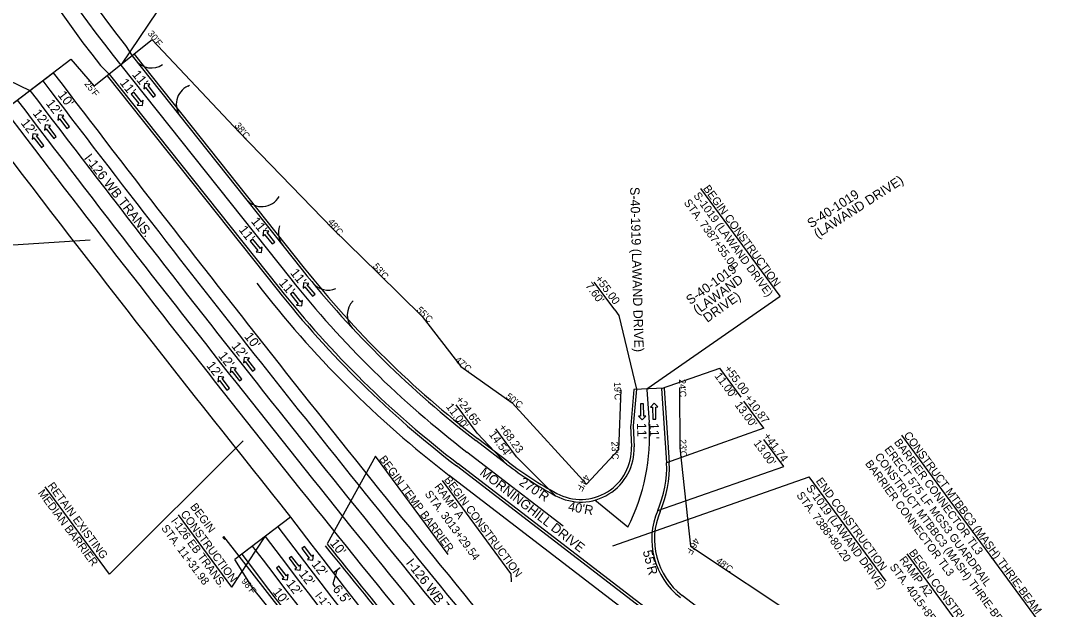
# Model space of a CAD drawing. Extents: x 1966090 to 1975830, y 788086 to 801233.
# Drawn here: x 1969648 to 1970416, y 797669 to 798102 of the extents above; entities that cross this region are included whole.
import ezdxf

# ---------------------------------------------------------------- set-up
doc = ezdxf.new("R2010")
doc.units = 0
for name, color, linetype in [('BR_PRESTRESSED BEAM', 7, 'Continuous'), ('BR_PROPOSED_DRAINAGE', 7, 'Continuous'), ('RD_EX_Driveway_txCode', 7, 'Continuous'), ('RD_EX_RW_TX', 7, 'Continuous'), ('RD_EX_SU_Gas', 7, 'Continuous'), ('RD_EX_SU_H2O', 7, 'Continuous'), ('RD_EX_Survey_Limits', 7, 'Continuous'), ('RD_EX_TX_Dam_ELEV', 7, 'Continuous'), ('RD_PD_PaveShd', 7, 'Continuous'), ('RD_PD_SuperShp2', 7, 'Continuous'), ('RD_Sketch4', 7, 'Continuous'), ('RD_Sketch6', 7, 'Continuous'), ('RD_Sketch8', 7, 'Continuous'), ('RD_Sketch9', 7, 'Continuous')]:
    doc.layers.add(name, color=color, linetype=linetype)

msp = doc.modelspace()

# ---------------------------------------------------------------- linework, layer by layer
at = {"layer": 'BR_PRESTRESSED BEAM'}
for p, q in [((1969800.02, 797714.91), (1969799.23, 797714.29)), ((1969799.23, 797714.29), (1969800.66, 797712.87)), ((1969801.25, 797713.33), (1969800.02, 797714.91)), ((1969844.28, 797658.12), (1969800.02, 797714.91)), ((1969800.66, 797712.87), (1969801.25, 797713.33))]:
    msp.add_line(p, q, dxfattribs=at)
at = {"layer": 'BR_PROPOSED_DRAINAGE'}
for p, q in [((1969746.43, 798087.34), (1969702.87, 798052.71)), ((1969746.43, 798087.34), (1969811.88, 798018)), ((1969620.66, 798023.58), (1969685.48, 798072.84)), ((1969685.48, 798072.84), (1969702.87, 798052.71)), ((1969811.88, 798018), (1969881.77, 797945.81)), ((1969881.77, 797945.81), (1969915.76, 797912.56)), ((1969915.76, 797912.56), (1969948.84, 797879.91)), ((1969948.84, 797879.91), (1969977.8, 797842.54)), ((1969977.8, 797842.54), (1970016.25, 797815.18)), ((1970097.89, 797824.97), (1970095.96, 797779.88)), ((1970141.67, 797826.51), (1970142.06, 797781.49)), ((1970072.06, 797754.16), (1970016.25, 797815.18)), ((1970095.96, 797779.88), (1970072.06, 797754.16)), ((1970142.06, 797781.49), (1970150.13, 797707.64)), ((1969850.13, 797729.55), (1969808.29, 797697.75)), ((1970150.13, 797707.64), (1970257.33, 797636.55)), ((1969822.69, 797674.98), (1969808.29, 797697.75)), ((1969822.69, 797674.98), (1969851.02, 797639.66))]:
    msp.add_line(p, q, dxfattribs=at)
msp.add_arc((1981199.22, 806822.99), 14542.78, 217.233941, 218.703425, dxfattribs=at)
at = {"layer": 'RD_EX_Driveway_txCode'}
for points in [[(1969747.1, 798044.55), (1969748.98, 798046.03), (1969743.32, 798053.24), (1969744.6, 798054.25), (1969740.63, 798054.72), (1969740.15, 798050.75), (1969741.43, 798051.76)], [(1969732.6, 798048.27), (1969730.72, 798046.78), (1969736.41, 798039.59), (1969735.13, 798038.58), (1969739.11, 798038.11), (1969739.57, 798042.09), (1969738.29, 798041.08)], [(1969682.46, 798020.92), (1969684.36, 798022.38), (1969678.77, 798029.65), (1969680.06, 798030.64), (1969676.1, 798031.16), (1969675.58, 798027.2), (1969676.87, 798028.19)], [(1969672.58, 798013.53), (1969674.48, 798014.99), (1969668.89, 798022.26), (1969670.19, 798023.26), (1969666.22, 798023.78), (1969665.7, 798019.81), (1969666.99, 798020.8)], [(1969663.3, 798006.67), (1969665.2, 798008.14), (1969659.61, 798015.41), (1969660.91, 798016.4), (1969656.94, 798016.92), (1969656.42, 798012.96), (1969657.71, 798013.95)], [(1969836.35, 797934.34), (1969838.23, 797935.82), (1969832.57, 797943.03), (1969833.85, 797944.04), (1969829.88, 797944.52), (1969829.4, 797940.55), (1969830.68, 797941.55)], [(1969821.85, 797938.06), (1969819.97, 797936.57), (1969825.66, 797929.38), (1969824.38, 797928.37), (1969828.36, 797927.91), (1969828.82, 797931.88), (1969827.54, 797930.87)], [(1969866.67, 797895.18), (1969868.52, 797896.72), (1969862.66, 797903.78), (1969863.92, 797904.82), (1969859.93, 797905.19), (1969859.56, 797901.2), (1969860.82, 797902.24)], [(1969852.08, 797898.17), (1969850.2, 797896.69), (1969855.86, 797889.48), (1969854.58, 797888.47), (1969858.55, 797887.99), (1969859.03, 797891.97), (1969857.75, 797890.96)], [(1969821.63, 797838.98), (1969823.53, 797840.45), (1969817.95, 797847.72), (1969819.24, 797848.71), (1969815.27, 797849.23), (1969814.75, 797845.27), (1969816.04, 797846.26)], [(1969811.75, 797831.6), (1969813.66, 797833.06), (1969808.07, 797840.33), (1969809.36, 797841.32), (1969805.39, 797841.84), (1969804.87, 797837.88), (1969806.16, 797838.87)], [(1969802.47, 797824.74), (1969804.38, 797826.2), (1969798.79, 797833.48), (1969800.08, 797834.47), (1969796.11, 797834.99), (1969795.59, 797831.02), (1969796.88, 797832.02)], [(1970114.87, 797814.49), (1970112.47, 797814.45), (1970112.63, 797805.28), (1970111, 797805.25), (1970113.88, 797802.47), (1970116.66, 797805.34), (1970115.03, 797805.32)], [(1970121.7, 797802.87), (1970124.1, 797802.91), (1970123.95, 797812.08), (1970125.58, 797812.11), (1970122.7, 797814.89), (1970119.92, 797812.02), (1970121.55, 797812.04)], [(1969860.47, 797707.37), (1969858.57, 797705.91), (1969864.15, 797698.64), (1969862.86, 797697.65), (1969866.83, 797697.13), (1969867.35, 797701.09), (1969866.06, 797700.1)], [(1969850.95, 797700.06), (1969849.05, 797698.6), (1969854.64, 797691.33), (1969853.34, 797690.34), (1969857.31, 797689.82), (1969857.83, 797693.78), (1969856.54, 797692.79)], [(1969841.44, 797692.75), (1969839.53, 797691.29), (1969845.12, 797684.02), (1969843.83, 797683.03), (1969847.79, 797682.51), (1969848.31, 797686.47), (1969847.02, 797685.48)]]:
    msp.add_lwpolyline(points, close=True, dxfattribs=at)
at = {"layer": 'RD_EX_SU_Gas'}
msp.add_line((1970103.12, 797721.97), (1970078.27, 797742.23), dxfattribs=at)
for centre, radius, end in [((1981199.22, 806822.99), 14500, 219.566224), ((1981199.22, 806822.99), 14512, 219.566224), ((1978986.99, 804673.34), 11488, 219.351802), ((1978986.99, 804673.34), 11500, 219.351802)]:
    msp.add_arc(centre, radius, 217.233941, end, dxfattribs=at)
at = {"layer": 'RD_EX_Survey_Limits'}
for p, q in [((1969717.03, 798075.77), (1969722.78, 798068.54)), ((1969722.78, 798068.54), (1969850.24, 797908.19)), ((1970117.23, 797825.26), (1970118.99, 797800.47)), ((1970054.6, 797722.82), (1969982.43, 797778.22))]:
    msp.add_line(p, q, dxfattribs=at)
for centre, radius, start, end in [((1970357.34, 798584.73), 817.94, 194.81615, 218.48003), ((1970445.19, 798381.1), 760, 218.48003, 232.49072), ((1969969.37, 797789.87), 150, 333.08573, 4.0555)]:
    msp.add_arc(centre, radius, start, end, dxfattribs=at)
at = {"layer": 'RD_EX_TX_Dam_ELEV'}
msp.add_line((1970237.44, 797554.75), (1969969.03, 797760.77), dxfattribs=at)
msp.add_arc((1970445.19, 798381.1), 782, 217.51585, 232.49072, dxfattribs=at)
at = {"layer": 'RD_PD_PaveShd'}
for p, q in [((1969732.96, 798076.63), (1969860.41, 797916.28)), ((1969712.61, 798060.45), (1969840.06, 797900.1)), ((1970107.6, 797825.31), (1970105.18, 797798.25)), ((1970130.21, 797826.1), (1970134.16, 797770.38)), ((1970105.17, 797798), (1970105.73, 797782.15)), ((1970013.33, 797770.89), (1969990.34, 797788.53)), ((1970242.92, 797561.89), (1969974.51, 797767.91)), ((1970258.75, 797582.51), (1970143.72, 797670.81))]:
    msp.add_line(p, q, dxfattribs=at)
for centre, radius, start, end in [((1981199.22, 806822.99), 14478, 217.233941, 219.566224), ((1970445.19, 798381.1), 747, 218.48003, 232.49072), ((1970445.19, 798381.1), 773, 218.48003, 232.49072), ((1970067.75, 797780.82), 38, 241.77956, 2.0052), ((1970176.51, 797983.48), 268, 232.49072, 241.77956), ((1970049.21, 797767.37), 85, 336.73101, 2.02947), ((1970175.99, 797712.85), 53, 156.73101, 232.49072), ((1978986.99, 804673.34), 11522, 217.233941, 219.351802)]:
    msp.add_arc(centre, radius, start, end, dxfattribs=at)
at = {"layer": 'RD_PD_SuperShp2'}
for p, q in [((1969884.77, 797689.52), (1969881.78, 797679.44)), ((1969887.34, 797691.49), (1969882.2, 797687.55)), ((1969881.78, 797679.44), (1969883.33, 797677.34))]:
    msp.add_line(p, q, dxfattribs=at)
at = {"layer": 'RD_Sketch4'}
msp.add_line((1969773.03, 798052.68), (1969774.42, 798053.34), dxfattribs=at)
for centre, start, end in [((1969745.86, 798081.36), 218.47031, 303.81397), ((1969779.43, 798039.12), 115.24627, 218.47031), ((1969828.49, 797977.37), 218.47031, 330.71955), ((1969855.99, 797942.76), 160.04461, 218.47031), ((1969878.39, 797914.72), 219.44849, 292.71218), ((1969907.66, 797881.27), 135.2692, 222.91891)]:
    msp.add_arc(centre, 15, start, end, dxfattribs=at)
at = {"layer": 'RD_Sketch6'}
for p, q in [((1969825.05, 798219.92), (1969722.78, 798068.54)), ((1969554.27, 798097.16), (1969654.73, 798049.47)), ((1970217.33, 797895.18), (1970157.87, 797975.84)), ((1969699.8, 797937.27), (1969608.11, 797931.2)), ((1970093.23, 797884.86), (1970077.81, 797905.77)), ((1970117.21, 797825.65), (1970217.33, 797895.18)), ((1970188.08, 797819.44), (1970171.99, 797841.27)), ((1969989.98, 797792.53), (1969974.36, 797813.71)), ((1970205.08, 797796.1), (1970190.11, 797816.4)), ((1970019.64, 797774.64), (1970004.02, 797795.82)), ((1970308.2, 797791.08), (1970416.24, 797644.53)), ((1969814.54, 797786.76), (1969714.47, 797686.6)), ((1970220.1, 797767.5), (1970205.13, 797787.82)), ((1969913.95, 797775.1), (1969877.62, 797709.35)), ((1969968.28, 797701.39), (1969913.95, 797775.1)), ((1970019.64, 797774.64), (1970048.84, 797745.58)), ((1970091.92, 797708.05), (1970239.06, 797759.74)), ((1970296.7, 797681.54), (1970239.06, 797759.74)), ((1969714.47, 797686.6), (1969666.13, 797752.19)), ((1970015.34, 797687.23), (1969964, 797756.86)), ((1969806.09, 797676.96), (1969766.06, 797731.26)), ((1969806.09, 797676.96), (1969831.02, 797715.03)), ((1970365.39, 797630.1), (1970312.42, 797701.95)), ((1970015.34, 797687.23), (1970015.61, 797681.01))]:
    msp.add_line(p, q, dxfattribs=at)
for points in [[(1970093.23, 797884.86), (1970096.35, 797880.64), (1970109.62, 797825.38)], [(1970128.21, 797826.03), (1970171.99, 797841.27)], [(1969989.98, 797792.53), (1970012.11, 797769.31)], [(1970205.08, 797796.1), (1970132.16, 797770.27)], [(1970125.46, 797734.58), (1970220.1, 797767.5)]]:
    msp.add_lwpolyline(points, dxfattribs=at)
at = {"layer": 'RD_Sketch8'}
for p, q in [((1969726.43, 798083.24), (1969731.4, 798075.38)), ((1969731.4, 798075.38), (1969858.85, 797915.04)), ((1969707.64, 798068.31), (1969714.17, 798061.7)), ((1969635.62, 798034.94), (1969672.24, 798062.78)), ((1969714.17, 798061.7), (1969841.63, 797901.35)), ((1970109.62, 797825.38), (1970107.17, 797798.07)), ((1970130.21, 797826.1), (1970107.6, 797825.31)), ((1970128.21, 797826.03), (1970132.16, 797770.27)), ((1970107.17, 797798.07), (1970107.73, 797782.22)), ((1970012.11, 797769.31), (1969989.13, 797786.95)), ((1970244.13, 797563.47), (1969975.73, 797769.5)), ((1969850.13, 797729.55), (1969813.5, 797701.71))]:
    msp.add_line(p, q, dxfattribs=at)
for centre, radius, start, end in [((1970357.34, 798584.73), 805.94, 194.81615, 218.48003), ((1970357.34, 798584.73), 829.94, 194.81615, 218.48003), ((1981199.22, 806822.99), 14488, 217.233941, 219.492805), ((1981199.22, 806822.99), 14524, 217.233941, 219.566224), ((1970445.19, 798381.1), 749, 218.48003, 232.49072), ((1970445.19, 798381.1), 771, 218.48003, 232.49072), ((1970067.75, 797780.82), 40, 241.77956, 2.0052), ((1970176.51, 797983.48), 270, 232.49072, 241.77956), ((1970049.21, 797767.37), 83, 336.73101, 2.0052), ((1978986.99, 804673.34), 11476, 217.233941, 219.351802), ((1970175.99, 797712.85), 55, 156.73101, 232.49072), ((1978986.99, 804673.34), 11512, 217.233941, 219.351802)]:
    msp.add_arc(centre, radius, start, end, dxfattribs=at)
at = {"layer": 'RD_Sketch9'}
for radius in [14536, 14534]:
    msp.add_arc((1981199.22, 806822.99), radius, 218.833328, 219.566224, dxfattribs=at)

# ---------------------------------------------------------------- texts
at = {"layer": 'RD_EX_Driveway_txCode'}
for s, rotation, p in [("11'", 308.64673, (1969730.91, 798061.33)), ("11'", 307.53305, (1969721.7, 798055.14)), ("10'", 307.53142, (1969675.23, 798045.97)), ("12'", 307.53142, (1969666.31, 798039.64)), ("12'", 307.53142, (1969647.5, 798025)), ("12'", 307.53142, (1969656.43, 798032.25)), ("11'", 308.64673, (1969820.16, 797951.13)), ("11'", 307.53305, (1969810.95, 797944.94)), ("11'", 308.24073, (1969849.53, 797912.52)), ("11'", 310.16708, (1969840.9, 797904.92)), ("10'", 307.53142, (1969815.11, 797864.81)), ("12'", 307.53142, (1969805.48, 797857.71)), ("12'", 307.53142, (1969795.6, 797850.32)), ("12'", 307.53142, (1969786.68, 797843.07)), ("11'", 271.80335, (1970109.88, 797800.15)), ("11'", 271.80335, (1970119.21, 797800.04)), ("10'", 307.53305, (1969879.31, 797709.81)), ('I-126 WB TRANS.', 307.99228, (1969936.26, 797695.05)), ("12'", 307.53142, (1969855.98, 797686.76)), ("12'", 307.53142, (1969865.49, 797694.07)), ("12'", 307.53142, (1969846.46, 797679.45)), ("10'", 307.53305, (1969836.37, 797673.29))]:
    msp.add_text(s, height=7, rotation=rotation, dxfattribs=at).set_placement(p)
at = {"layer": 'RD_EX_RW_TX'}
for s, rotation, p in [("30'F", 308.48003, (1969742.68, 798092.06)), ("25'F", 308.48003, (1969695.2, 798054.32)), ("38'C", 308.48003, (1969807.89, 798023.02)), ("48'C", 308.48003, (1969877.78, 797950.83)), ("53'C", 311.5084, (1969911.52, 797917.36)), ("55'C", 315.27786, (1969944.29, 797884.42)), ("47'C", 319.04731, (1969972.97, 797846.74)), ("19'C", 272.0052, (1970092.69, 797830.72)), ("24'C", 272.0052, (1970141.45, 797832.91)), ("50'C", 322.49072, (1970011.17, 797819.08)), ("23'C", 272.0052, (1970090.74, 797786.1)), ("23'C", 272.0052, (1970141.84, 797787.89)), ("44'F", 239.9738, (1970070.75, 797761.88)), ("46'F", 239.9738, (1970152.99, 797714.36)), ("48'C", 322.49072, (1970168.79, 797695.79)), ("98'F", 308.78338, (1969812.89, 797681.32))]:
    msp.add_text(s, height=5, rotation=rotation, dxfattribs=at).set_placement(p)
at = {"layer": 'RD_EX_SU_H2O'}
for s, rotation, p in [('I-126 WB TRANS.', 307.99228, (1969694.85, 797998.62)), ('(LAWAND DRIVE)', 32.85686, (1970245.39, 797938.33)), ('S-40-1919 (LAWAND DRIVE)', 271.49911, (1970104.76, 797976.98)), ('S-40-1019 ', 32.85686, (1970240.41, 797946.03)), ('S-40-1019 ', 35.70029, (1970149.82, 797888.49)), ('(LAWAND', 35.70029, (1970155.18, 797881.04)), (' DRIVE)', 35.70029, (1970160.53, 797873.59)), ('MORNINGHILL DRIVE', 322.07869, (1969991.44, 797761.77))]:
    msp.add_text(s, height=7, rotation=rotation, dxfattribs=at).set_placement(p)
at = {"layer": 'RD_PD_SuperShp2'}
msp.add_text("6.5'", height=7, rotation=307.53142, dxfattribs=at).set_placement((1969881.38, 797675.42))
at = {"layer": 'RD_Sketch6'}
for s, height, rotation, p in [('BEGIN CONSTRUCTION', 5.9996, 306.06581, (1970159.23, 797975.91)), ('STA. 7387+55.00', 5.9996, 306.06581, (1970144.68, 797965.31)), ('S-1019 (LAWAND DRIVE)', 5.9996, 306.06581, (1970151.96, 797970.61)), ("7.60'", 6, 306.39766, (1970070.89, 797902.9)), ('+55.00', 6, 306.39766, (1970078.14, 797908.24)), ("11.00'", 6, 306.39766, (1970167.75, 797835.34)), ('+55.00', 6, 306.39766, (1970174.99, 797840.68)), ('+10.87', 6, 306.39766, (1970190.13, 797818.88)), ("11.00'", 6, 306.39766, (1969966.36, 797812.3)), ('+24.65', 6, 306.39766, (1969973.61, 797817.64)), ("13.00'", 6, 306.39766, (1970182.88, 797813.54)), ('+68.23', 6, 306.39766, (1970005.85, 797796.79)), ("14.54'", 6, 306.39766, (1969998.61, 797791.45)), ('+41.74', 6, 306.39766, (1970204.23, 797790.17)), ('CONSTRUCT MTBBC3 (MASH) THRIE-BEAM', 5.9996, 306.42425, (1970309.64, 797790.96)), ("13.00'", 6, 306.39766, (1970196.99, 797784.83)), ('ERECT 575 LF MGS3 GUARDRAIL', 5.9996, 306.42425, (1970295.16, 797780.27)), ('BARRIER CONNECTOR TL3', 5.9996, 306.42425, (1970302.4, 797785.61)), ('BEGIN TEMP BARRIER', 5.9996, 306.55749, (1969916.26, 797772.95)), ('CONSTRUCT MTBBC3 (MASH) THRIE-BEAM', 5.9996, 306.42425, (1970287.92, 797774.93)), ('BARRIER CONNECTOR TL3', 5.9996, 306.42425, (1970280.68, 797769.58)), ('BEGIN CONSTRUCTION', 5.9996, 306.55916, (1969964.9, 797757.54)), ("270'R", 7, 326.29483, (1970020.96, 797754.11)), ('END CONSTRUCTION', 5.9996, 306.06581, (1970243.74, 797756.49)), ('RETAIN EXISTING', 5.9996, 306.5592, (1969667.63, 797752.94)), ('RAMP A', 6, 306.55916, (1969957.67, 797752.18)), ('S-1019 (LAWAND DRIVE)', 5.9996, 306.06581, (1970236.46, 797751.2)), ('MEDIAN BARRIER', 5.9996, 306.5592, (1969660.4, 797747.58)), ('STA. 3013+29.54', 5.9996, 306.55916, (1969950.44, 797746.82)), ('STA. 7388+80.20', 5.9996, 306.06581, (1970229.19, 797745.9)), ('BEGIN ', 6, 306.55916, (1969774.58, 797737.26)), ("40'R", 7, 349.58216, (1970057.91, 797734.39)), ('I-126 EB TRANS.', 5.9996, 306.55916, (1969760.12, 797726.54)), ('CONSTRUCTION', 5.9996, 306.55916, (1969767.35, 797731.9)), ('STA. 11+31.98', 5.9996, 306.55916, (1969752.89, 797721.18)), ('BEGIN CONSTRUCTION', 5.9996, 306.55916, (1970313.51, 797702.77)), ("55'R", 7, 284.21093, (1970114.19, 797703.81)), ('RAMP A2 ', 6, 306.55916, (1970306.28, 797697.41)), ('STA. 4015+85.70', 5.9996, 306.55916, (1970299.05, 797692.05)), ('I-126 EB TRANS.', 5.9996, 307.35236, (1969868.15, 797670.55))]:
    msp.add_text(s, height=height, rotation=rotation, dxfattribs=at).set_placement(p)

doc.saveas('drawing.dxf')
